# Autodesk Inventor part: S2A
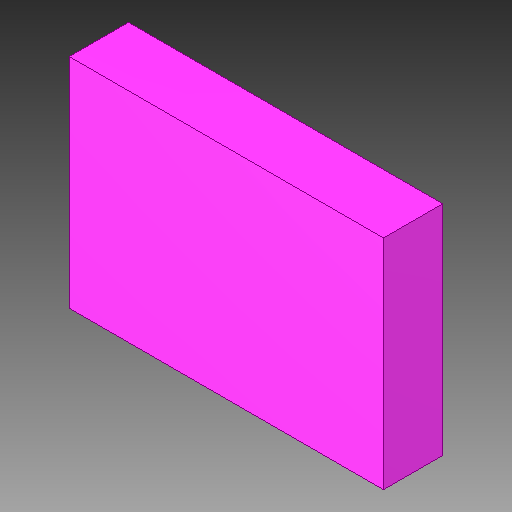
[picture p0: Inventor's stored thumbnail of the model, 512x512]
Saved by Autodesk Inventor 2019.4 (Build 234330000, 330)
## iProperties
Created: 2019-11
Part Number: S2A
Material: Generic
Document SubType Name: Modeling
Designer: Willist
Density: 1 g/cm^3
Appearance: DO214AA, S2A
Author: Willist
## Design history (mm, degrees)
sketch "DO214AA, S2A_137"
  geometry: L1 (-2.65, 1.876)-(2.65, 1.876); L2 (2.65, 1.876)-(2.65, -1.8); L3 (2.65, -1.8)-(-2.65, -1.8); L4 (-2.65, -1.8)-(-2.65, 1.876)
  constraints: 8 end point
extrude "Extrusion1" join sketch "DO214AA, S2A_137" distance "d0" = 1; taper "d1" = 0 deg
body "Solid1"
